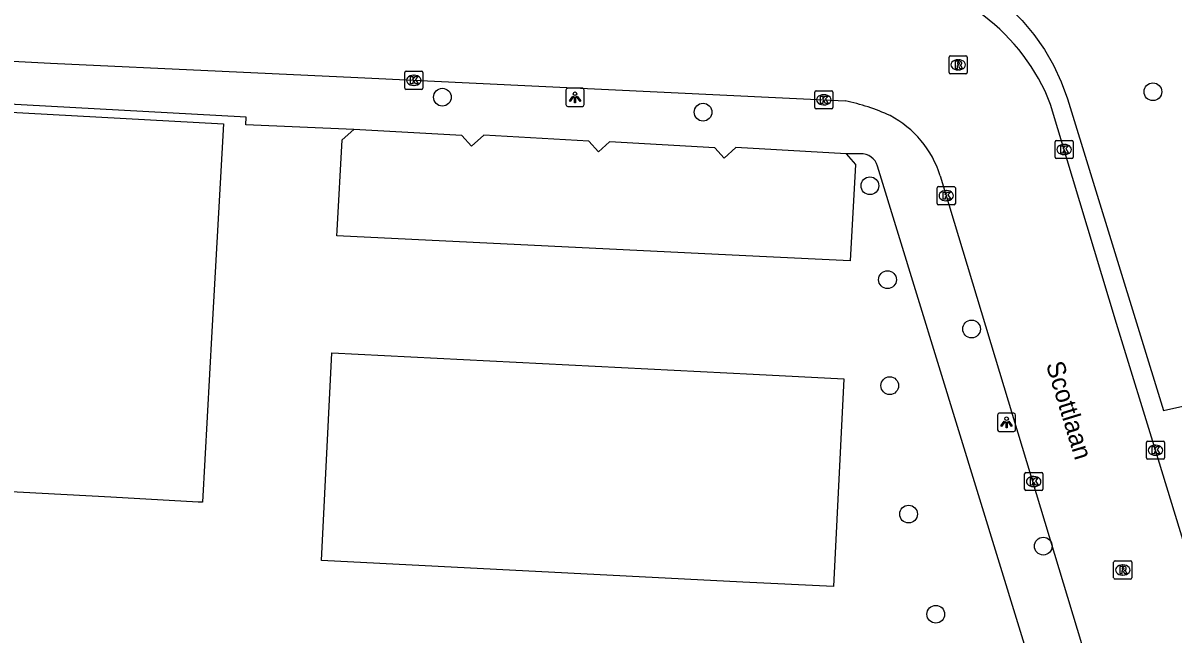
# Model space of a CAD drawing. Extents: x 161253 to 161848, y 384872 to 385383.
# Drawn here: x 161391.4 to 161454.7, y 384915.7 to 384949.4 of the extents above; entities that cross this region are included whole.
import ezdxf

# ---------------------------------------------------------------- set-up
doc = ezdxf.new("R2010")
doc.units = 0
for name, color, linetype in [('IMGEO_Boom', 7, 'Continuous'), ('IMGEO_Kolk', 7, 'Continuous'), ('IMGEO_Lichtpunt', 7, 'Continuous'), ('IMGEO_Openbare_ruimte_label', 7, 'Continuous'), ('IMGEO_Pand', 7, 'Continuous'), ('IMGEO_Rijbaan_lokaal_open', 7, 'Continuous'), ('IMGEO_Rioolput', 7, 'Continuous'), ('IMGEO_Voetpad_open', 7, 'Continuous')]:
    doc.layers.add(name, color=color, linetype=linetype)

msp = doc.modelspace()

# ---------------------------------------------------------------- linework, layer by layer
at = {"layer": 'IMGEO_Boom'}
for centre in [(161414.473, 384945.329), (161453.642, 384945.628), (161428.842, 384944.505), (161438.042, 384940.448), (161439.011, 384935.274), (161443.647, 384932.556), (161439.133, 384929.434), (161440.172, 384922.359), (161447.598, 384920.591), (161441.673, 384916.84)]:
    msp.add_circle(centre, 0.489, dxfattribs=at)
at = {"layer": 'IMGEO_Kolk'}
for p, q in [((161412.4, 384945.835), (161412.4, 384946.687)), ((161412.475, 384946.761), (161413.327, 384946.761)), ((161412.888, 384946.541), (161412.913, 384946.541)), ((161413.401, 384946.687), (161413.401, 384945.835)), ((161413.327, 384945.761), (161412.475, 384945.761)), ((161412.911, 384945.981), (161412.886, 384945.981)), ((161434.997, 384944.762), (161434.997, 384945.614)), ((161435.072, 384945.688), (161435.924, 384945.688)), ((161435.998, 384945.614), (161435.998, 384944.762)), ((161435.485, 384945.468), (161435.51, 384945.468)), ((161435.924, 384944.688), (161435.072, 384944.688)), ((161435.508, 384944.908), (161435.483, 384944.908)), ((161448.251, 384942.021), (161448.251, 384942.873)), ((161448.326, 384942.947), (161449.178, 384942.947)), ((161448.739, 384942.727), (161448.764, 384942.727)), ((161449.252, 384942.873), (161449.252, 384942.021)), ((161449.178, 384941.947), (161448.326, 384941.947)), ((161448.762, 384942.167), (161448.737, 384942.167)), ((161441.75, 384939.476), (161441.75, 384940.328)), ((161441.825, 384940.402), (161442.677, 384940.402)), ((161442.238, 384940.182), (161442.263, 384940.182)), ((161442.751, 384940.328), (161442.751, 384939.476)), ((161442.677, 384939.402), (161441.825, 384939.402)), ((161442.261, 384939.622), (161442.236, 384939.622)), ((161453.281, 384925.45), (161453.281, 384926.302)), ((161453.356, 384926.376), (161454.208, 384926.376)), ((161453.769, 384926.156), (161453.794, 384926.156)), ((161454.282, 384926.302), (161454.282, 384925.45)), ((161454.208, 384925.376), (161453.356, 384925.376)), ((161453.792, 384925.596), (161453.767, 384925.596)), ((161446.569, 384923.724), (161446.569, 384924.576)), ((161446.644, 384924.65), (161447.496, 384924.65)), ((161447.057, 384924.43), (161447.082, 384924.43)), ((161447.57, 384924.576), (161447.57, 384923.724)), ((161447.496, 384923.65), (161446.644, 384923.65)), ((161447.08, 384923.87), (161447.055, 384923.87))]:
    msp.add_line(p, q, dxfattribs=at)
for points in [[(161412.4, 384945.835), (161412.4, 384946.687)], [(161412.475, 384946.761), (161413.327, 384946.761)], [(161412.721, 384946.461), (161412.844, 384946.461), (161412.844, 384946.31), (161412.974, 384946.461), (161413.138, 384946.461), (161412.992, 384946.31), (161413.145, 384946.061), (161412.993, 384946.061), (161412.908, 384946.225), (161412.844, 384946.158), (161412.844, 384946.061), (161412.721, 384946.061), (161412.721, 384946.461)], [(161413.401, 384946.687), (161413.401, 384945.835)], [(161413.327, 384945.761), (161412.475, 384945.761)], [(161434.997, 384944.762), (161434.997, 384945.614)], [(161435.072, 384945.688), (161435.924, 384945.688)], [(161435.998, 384945.614), (161435.998, 384944.762)], [(161435.318, 384945.388), (161435.441, 384945.388), (161435.441, 384945.237), (161435.571, 384945.388), (161435.735, 384945.388), (161435.589, 384945.237), (161435.742, 384944.988), (161435.59, 384944.988), (161435.505, 384945.152), (161435.441, 384945.085), (161435.441, 384944.988), (161435.318, 384944.988), (161435.318, 384945.388)], [(161435.924, 384944.688), (161435.072, 384944.688)], [(161448.251, 384942.021), (161448.251, 384942.873)], [(161448.326, 384942.947), (161449.178, 384942.947)], [(161448.572, 384942.647), (161448.695, 384942.647), (161448.695, 384942.496), (161448.825, 384942.647), (161448.989, 384942.647), (161448.843, 384942.496), (161448.996, 384942.247), (161448.844, 384942.247), (161448.759, 384942.411), (161448.695, 384942.344), (161448.695, 384942.247), (161448.572, 384942.247), (161448.572, 384942.647)], [(161449.252, 384942.873), (161449.252, 384942.021)], [(161449.178, 384941.947), (161448.326, 384941.947)], [(161441.75, 384939.476), (161441.75, 384940.328)], [(161441.825, 384940.402), (161442.677, 384940.402)], [(161442.071, 384940.102), (161442.194, 384940.102), (161442.194, 384939.951), (161442.324, 384940.102), (161442.488, 384940.102), (161442.342, 384939.951), (161442.495, 384939.702), (161442.343, 384939.702), (161442.258, 384939.866), (161442.194, 384939.799), (161442.194, 384939.702), (161442.071, 384939.702), (161442.071, 384940.102)], [(161442.751, 384940.328), (161442.751, 384939.476)], [(161442.677, 384939.402), (161441.825, 384939.402)], [(161453.281, 384925.45), (161453.281, 384926.302)], [(161453.356, 384926.376), (161454.208, 384926.376)], [(161453.602, 384926.076), (161453.725, 384926.076), (161453.725, 384925.925), (161453.855, 384926.076), (161454.019, 384926.076), (161453.873, 384925.925), (161454.026, 384925.676), (161453.874, 384925.676), (161453.789, 384925.84), (161453.725, 384925.773), (161453.725, 384925.676), (161453.602, 384925.676), (161453.602, 384926.076)], [(161454.282, 384926.302), (161454.282, 384925.45)], [(161454.208, 384925.376), (161453.356, 384925.376)], [(161446.569, 384923.724), (161446.569, 384924.576)], [(161446.644, 384924.65), (161447.496, 384924.65)], [(161446.89, 384924.35), (161447.013, 384924.35), (161447.013, 384924.199), (161447.143, 384924.35), (161447.307, 384924.35), (161447.161, 384924.199), (161447.314, 384923.95), (161447.162, 384923.95), (161447.077, 384924.114), (161447.013, 384924.047), (161447.013, 384923.95), (161446.89, 384923.95), (161446.89, 384924.35)], [(161447.57, 384924.576), (161447.57, 384923.724)], [(161447.496, 384923.65), (161446.644, 384923.65)]]:
    msp.add_lwpolyline(points, dxfattribs=at)
for centre, start, end in [((161412.477, 384946.685), 91.55205, 178.44795), ((161412.477, 384946.685), 91.55205, 178.44795), ((161413.325, 384946.685), 1.55205, 88.44795), ((161413.325, 384946.685), 1.55205, 88.44795), ((161412.477, 384945.837), 181.55205, 268.44795), ((161412.477, 384945.837), 181.55205, 268.44795), ((161413.325, 384945.837), 271.55205, 358.44795), ((161413.325, 384945.837), 271.55205, 358.44795), ((161435.074, 384945.612), 91.55205, 178.44795), ((161435.074, 384945.612), 91.55205, 178.44795), ((161435.922, 384945.612), 1.55205, 88.44795), ((161435.922, 384945.612), 1.55205, 88.44795), ((161435.074, 384944.764), 181.55205, 268.44795), ((161435.074, 384944.764), 181.55205, 268.44795), ((161435.922, 384944.764), 271.55205, 358.44795), ((161435.922, 384944.764), 271.55205, 358.44795), ((161448.328, 384942.871), 91.55205, 178.44795), ((161448.328, 384942.871), 91.55205, 178.44795), ((161449.176, 384942.871), 1.55205, 88.44795), ((161449.176, 384942.871), 1.55205, 88.44795), ((161448.328, 384942.023), 181.55205, 268.44795), ((161448.328, 384942.023), 181.55205, 268.44795), ((161449.176, 384942.023), 271.55205, 358.44795), ((161449.176, 384942.023), 271.55205, 358.44795), ((161441.827, 384940.326), 91.55205, 178.44795), ((161441.827, 384940.326), 91.55205, 178.44795), ((161442.675, 384940.326), 1.55205, 88.44795), ((161442.675, 384940.326), 1.55205, 88.44795), ((161441.827, 384939.478), 181.55205, 268.44795), ((161441.827, 384939.478), 181.55205, 268.44795), ((161442.675, 384939.478), 271.55205, 358.44795), ((161442.675, 384939.478), 271.55205, 358.44795), ((161453.358, 384926.3), 91.55205, 178.44795), ((161453.358, 384926.3), 91.55205, 178.44795), ((161454.206, 384926.3), 1.55205, 88.44795), ((161454.206, 384926.3), 1.55205, 88.44795), ((161453.358, 384925.452), 181.55205, 268.44795), ((161453.358, 384925.452), 181.55205, 268.44795), ((161454.206, 384925.452), 271.55205, 358.44795), ((161454.206, 384925.452), 271.55205, 358.44795), ((161446.646, 384924.574), 91.55205, 178.44795), ((161446.646, 384924.574), 91.55205, 178.44795), ((161447.494, 384924.574), 1.55205, 88.44795), ((161447.494, 384924.574), 1.55205, 88.44795), ((161446.646, 384923.726), 181.55205, 268.44795), ((161446.646, 384923.726), 181.55205, 268.44795), ((161447.494, 384923.726), 271.55205, 358.44795), ((161447.494, 384923.726), 271.55205, 358.44795)]:
    msp.add_arc(centre, 0.0765, start, end, dxfattribs=at)
for centre, major_axis, ratio, start_param, end_param in [((161412.887, 384946.261), (-0.387, 0.002), 0.722429, 4.712389, 7.853982), ((161412.912, 384946.261), (-0.39, 0.002), 0.717154, 1.570796, 4.712389), ((161435.484, 384945.188), (-0.387, 0.002), 0.722429, 4.712389, 7.853982), ((161435.509, 384945.188), (-0.39, 0.002), 0.717154, 1.570796, 4.712389), ((161448.738, 384942.447), (-0.387, 0.002), 0.722429, 4.712389, 7.853982), ((161448.763, 384942.447), (-0.39, 0.002), 0.717154, 1.570796, 4.712389), ((161442.237, 384939.902), (-0.387, 0.002), 0.722429, 4.712389, 7.853982), ((161442.262, 384939.902), (-0.39, 0.002), 0.717154, 1.570796, 4.712389), ((161453.768, 384925.876), (-0.387, 0.002), 0.722429, 4.712389, 7.853982), ((161453.793, 384925.876), (-0.39, 0.002), 0.717154, 1.570796, 4.712389), ((161447.056, 384924.15), (-0.387, 0.002), 0.722429, 4.712389, 7.853982), ((161447.081, 384924.15), (-0.39, 0.002), 0.717154, 1.570796, 4.712389)]:
    msp.add_ellipse(centre, major_axis=major_axis, ratio=ratio, start_param=start_param, end_param=end_param, dxfattribs=at)
at = {"layer": 'IMGEO_Lichtpunt'}
for p, q in [((161421.288, 384945.726), (161421.288, 384944.919)), ((161421.288, 384945.726), (161421.288, 384944.919)), ((161422.19, 384945.821), (161421.382, 384945.821)), ((161422.19, 384945.821), (161421.382, 384945.821)), ((161422.284, 384944.919), (161422.284, 384945.726)), ((161422.284, 384944.919), (161422.284, 384945.726)), ((161421.382, 384944.825), (161422.19, 384944.825)), ((161421.382, 384944.825), (161422.19, 384944.825)), ((161445.978, 384927.91), (161445.17, 384927.91)), ((161445.978, 384927.91), (161445.17, 384927.91)), ((161445.076, 384927.815), (161445.076, 384927.008)), ((161445.076, 384927.815), (161445.076, 384927.008)), ((161446.072, 384927.008), (161446.072, 384927.815)), ((161446.072, 384927.008), (161446.072, 384927.815)), ((161445.17, 384926.914), (161445.978, 384926.914)), ((161445.17, 384926.914), (161445.978, 384926.914))]:
    msp.add_line(p, q, dxfattribs=at)
for points in [[(161421.662, 384945.39), (161421.701, 384945.362), (161421.513, 384945.1), (161421.475, 384945.127), (161421.662, 384945.39)], [(161421.764, 384945.342), (161421.811, 384945.342), (161421.811, 384945.02), (161421.764, 384945.02), (161421.764, 384945.342)], [(161421.874, 384945.362), (161421.912, 384945.389), (161422.099, 384945.127), (161422.06, 384945.099), (161421.874, 384945.362)], [(161445.45, 384927.479), (161445.489, 384927.451), (161445.301, 384927.189), (161445.263, 384927.216), (161445.45, 384927.479)], [(161445.552, 384927.431), (161445.599, 384927.431), (161445.599, 384927.109), (161445.552, 384927.109), (161445.552, 384927.431)], [(161445.662, 384927.451), (161445.7, 384927.478), (161445.887, 384927.216), (161445.848, 384927.188), (161445.662, 384927.451)]]:
    msp.add_lwpolyline(points, dxfattribs=at)
for centre in [(161421.787, 384945.524), (161445.575, 384927.613)]:
    msp.add_circle(centre, 0.0994, dxfattribs=at)
for centre, start, end in [((161421.382, 384945.726), 90, 180), ((161421.382, 384945.726), 90, 180), ((161422.19, 384945.726), 0, 90), ((161422.19, 384945.726), 0, 90), ((161421.382, 384944.919), 180, 270), ((161421.382, 384944.919), 180, 270), ((161422.19, 384944.919), 270, 0), ((161422.19, 384944.919), 270, 360), ((161445.17, 384927.815), 90, 180), ((161445.17, 384927.815), 90, 180), ((161445.978, 384927.815), 0, 90), ((161445.978, 384927.815), 0, 90), ((161445.17, 384927.008), 180, 270), ((161445.17, 384927.008), 180, 270), ((161445.978, 384927.008), 270, 0), ((161445.978, 384927.008), 270, 360)]:
    msp.add_arc(centre, 0.0946, start, end, dxfattribs=at)
at = {"layer": 'IMGEO_Pand'}
for points in [[(161388.642, 384944.623), (161402.4, 384943.868), (161401.772, 384932.41), (161401.256, 384923.007)], [(161436.725, 384942.209), (161437.252, 384941.619), (161436.953, 384936.313), (161431.959, 384936.555), (161408.657, 384937.683), (161408.674, 384937.993), (161408.956, 384942.985), (161409.594, 384943.555)], [(161436.725, 384942.209), (161430.658, 384942.551), (161429.999, 384941.963), (161429.486, 384942.538), (161423.695, 384942.864), (161423.078, 384942.313), (161422.553, 384942.902), (161416.752, 384943.229), (161416.074, 384942.623), (161415.542, 384943.219), (161409.594, 384943.555)], [(161431.614, 384930.071), (161436.607, 384929.818), (161436.025, 384918.36), (161431.032, 384918.613), (161407.806, 384919.792), (161408.388, 384931.25), (161431.614, 384930.071)], [(161401.256, 384923.007), (161401.02, 384923.02), (161396.201, 384923.284), (161388.608, 384923.701)]]:
    msp.add_lwpolyline(points, dxfattribs=at)
at = {"layer": 'IMGEO_Rijbaan_lokaal_open'}
for points in [[(161364.492, 384948.607), (161367.746, 384948.524), (161392.878, 384947.213), (161402.342, 384946.764), (161409.808, 384946.409), (161436.678, 384945.133)], [(161460.368, 384904.332), (161458.507, 384910.295), (161456.119, 384918.262), (161453.927, 384925.402), (161451.635, 384932.866), (161448.004, 384944.929)], [(161441.917, 384941.001), (161451.731, 384908.54), (161452.061, 384907.353), (161452.677, 384905.212)]]:
    msp.add_lwpolyline(points, dxfattribs=at)
for centre, radius, start, end in [((161437.605, 384940.914), 11.147, 21.11028, 84.76396), ((161433.975, 384932.708), 12.716, 65.94248, 77.72887), ((161436.502, 384939.305), 5.674, 17.38774, 62.08058)]:
    msp.add_arc(centre, radius, start, end, dxfattribs=at)
at = {"layer": 'IMGEO_Rioolput'}
for p, q in [((161442.407, 384946.689), (161442.407, 384947.541)), ((161442.482, 384947.615), (161443.334, 384947.615)), ((161443.408, 384947.541), (161443.408, 384946.689)), ((161442.895, 384947.395), (161442.92, 384947.395)), ((161443.334, 384946.615), (161442.482, 384946.615)), ((161442.918, 384946.835), (161442.893, 384946.835)), ((161451.478, 384918.852), (161451.478, 384919.704)), ((161451.553, 384919.778), (161452.405, 384919.778)), ((161452.479, 384919.704), (161452.479, 384918.852)), ((161451.989, 384918.998), (161451.964, 384918.998)), ((161451.966, 384919.558), (161451.991, 384919.558)), ((161452.405, 384918.778), (161451.553, 384918.778))]:
    msp.add_line(p, q, dxfattribs=at)
for points in [[(161442.407, 384946.689), (161442.407, 384947.541)], [(161442.482, 384947.615), (161443.334, 384947.615)], [(161443.408, 384947.541), (161443.408, 384946.689)], [(161442.996, 384947.313), (161442.744, 384947.315), (161442.744, 384946.915)], [(161442.744, 384946.915), (161442.868, 384946.915), (161442.868, 384947.077), (161442.879, 384947.077)], [(161442.922, 384947.234), (161442.868, 384947.234), (161442.868, 384947.153)], [(161442.868, 384947.153), (161442.92, 384947.153)], [(161442.926, 384947.048), (161442.997, 384946.915), (161443.137, 384946.915), (161443.072, 384947.041)], [(161443.334, 384946.615), (161442.482, 384946.615)], [(161451.478, 384918.852), (161451.478, 384919.704)], [(161451.553, 384919.778), (161452.405, 384919.778)], [(161452.479, 384919.704), (161452.479, 384918.852)], [(161452.067, 384919.476), (161451.815, 384919.478), (161451.815, 384919.078)], [(161451.815, 384919.078), (161451.939, 384919.078), (161451.939, 384919.24), (161451.95, 384919.24)], [(161451.993, 384919.397), (161451.939, 384919.397), (161451.939, 384919.316)], [(161451.939, 384919.316), (161451.991, 384919.316)], [(161451.997, 384919.211), (161452.068, 384919.078), (161452.208, 384919.078), (161452.143, 384919.204)], [(161452.405, 384918.778), (161451.553, 384918.778)]]:
    msp.add_lwpolyline(points, dxfattribs=at)
for centre, radius, start, end in [((161442.484, 384947.539), 0.0765, 91.55205, 178.44795), ((161442.484, 384947.539), 0.0765, 91.55205, 178.44795), ((161443.332, 384947.539), 0.0765, 1.55205, 88.44795), ((161443.332, 384947.539), 0.0765, 1.55205, 88.44795), ((161442.878, 384947.024), 0.0533, 26.02933, 88.69889), ((161442.904, 384947.342), 0.19, 274.7715, 282.96867), ((161442.928, 384947.138), 0.0964, 77.00612, 93.18647), ((161442.942, 384947.195), 0.0378, 276.66336, 79.67722), ((161442.995, 384947.203), 0.109, 350.36119, 89.41601), ((161442.993, 384947.203), 0.112, 277.58423, 350.98172), ((161442.977, 384946.988), 0.108, 29.51342, 73.79051), ((161442.484, 384946.691), 0.0765, 181.55205, 268.44795), ((161442.484, 384946.691), 0.0765, 181.55205, 268.44795), ((161443.332, 384946.691), 0.0765, 271.55205, 358.44795), ((161443.332, 384946.691), 0.0765, 271.55205, 358.44795), ((161451.555, 384919.702), 0.0765, 91.55205, 178.44795), ((161451.555, 384919.702), 0.0765, 91.55205, 178.44795), ((161452.403, 384919.702), 0.0765, 1.55205, 88.44795), ((161452.403, 384919.702), 0.0765, 1.55205, 88.44795), ((161451.949, 384919.187), 0.0533, 26.02933, 88.69889), ((161451.975, 384919.505), 0.19, 274.7715, 282.96867), ((161451.999, 384919.301), 0.0964, 77.00612, 93.18647), ((161452.013, 384919.358), 0.0378, 276.66336, 79.67722), ((161452.066, 384919.366), 0.109, 350.36119, 89.41601), ((161452.064, 384919.366), 0.112, 277.58423, 350.98172), ((161452.048, 384919.151), 0.108, 29.51342, 73.79051), ((161451.555, 384918.854), 0.0765, 181.55205, 268.44795), ((161451.555, 384918.854), 0.0765, 181.55205, 268.44795), ((161452.403, 384918.854), 0.0765, 271.55205, 358.44795), ((161452.403, 384918.854), 0.0765, 271.55205, 358.44795)]:
    msp.add_arc(centre, radius, start, end, dxfattribs=at)
for centre, major_axis, ratio, start_param, end_param in [((161442.894, 384947.115), (-0.387, 0.002), 0.722429, 4.712389, 7.853982), ((161442.919, 384947.115), (-0.39, 0.002), 0.717154, 1.570796, 4.712389), ((161451.965, 384919.278), (-0.387, 0.002), 0.722429, 4.712389, 7.853982), ((161451.99, 384919.278), (-0.39, 0.002), 0.717154, 1.570796, 4.712389)]:
    msp.add_ellipse(centre, major_axis=major_axis, ratio=ratio, start_param=start_param, end_param=end_param, dxfattribs=at)
at = {"layer": 'IMGEO_Voetpad_open'}
for points in [[(161445.755, 384950.228), (161446.432, 384949.557), (161447.081, 384948.789), (161447.66, 384947.966), (161448.163, 384947.095), (161448.585, 384946.183), (161448.925, 384945.236), (161454.217, 384928.071), (161455.63, 384928.386), (161455.957, 384927.409)], [(161409.594, 384943.555), (161403.643, 384943.814), (161403.665, 384944.222), (161366.425, 384946.266), (161366.386, 384945.555), (161366.264, 384945.56)], [(161437.515, 384942.215), (161436.725, 384942.209)], [(161449.597, 384905.304), (161438.466, 384941.532)]]:
    msp.add_lwpolyline(points, dxfattribs=at)
msp.add_arc((161437.543, 384941.25), 0.965, 16.98768, 91.64116, dxfattribs=at)

# ---------------------------------------------------------------- texts
at = {"layer": 'IMGEO_Openbare_ruimte_label'}
msp.add_text('Scottlaan', height=1, rotation=287.03954, dxfattribs=at).set_placement((161447.735, 384930.606))

doc.saveas('drawing.dxf')
